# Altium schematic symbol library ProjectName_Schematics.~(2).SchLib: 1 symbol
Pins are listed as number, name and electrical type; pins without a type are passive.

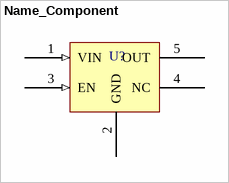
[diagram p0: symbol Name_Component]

## Name_Component
designator U?  (value not drawn)
Description Component
pins: 1 VIN (in), 2 GND (power), 3 EN (in), 4 NC, 5 OUT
